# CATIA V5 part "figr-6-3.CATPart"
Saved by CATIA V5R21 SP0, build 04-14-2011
Part number: Part1
Bounding box of the stored display mesh (mm): x -62.5 to 62.5, y -75 to 75, z 0 to 10
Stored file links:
  D:\CATIA V5R21 E-RESOURCES\CATIA-V5R21\catia-v5r21-prt\c06-catia-v5r21-prt\c06-catia-v5r21-figr-6-3.CATPart
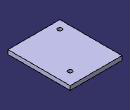
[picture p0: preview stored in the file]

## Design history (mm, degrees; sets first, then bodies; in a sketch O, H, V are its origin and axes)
Body1 (main body)
  Sketch1 on xy-plane, origin (0, 0, 0), H (1, 0, 0), V (0, 1, 0)
    line L1 (-62.5, 75) -> (62.5, 75)
    line L2 (62.5, 75) -> (62.5, -75)
    line L3 (62.5, -75) -> (-62.5, -75)
    line L4 (-62.5, -75) -> (-62.5, 75)
    axis line L5 (62.5, -75) -> (-62.5, 75)
    length L2 = 150
    length L3 = 125
    horizontal: L1 H, L3 H
    vertical: L2 V, L4 V
    midpoint: O L5
  Pad1: profile Sketch1, direction (0, 0, 1), length 10
  Sketch2 on face of Pad1, origin (-17.8347, -51.2044, 10), H (1, 0, 0), V (0, 1, 0)
    point P1 (-24.6653, -3.7956)
    reference projected line E1 (-44.6653, -23.7956) -> (80.3347, -23.7956) from edge [face of Pad1 | face of Pad1]
    reference projected line E2 (-44.6653, 126.2044) -> (-44.6653, -23.7956) from edge [face of Pad1 | face of Pad1]
    distance P1 E1 = 20
    distance P1 E2 = 20
  Hole1: placed by Sketch2, at (-42.5, -55, 10) direction (0, 0, -1), diameter 10, through (limit type 3)
  Sketch3 on face of Pad1, origin (35.5503, 42.9865, 10), H (1, 0, 0), V (0, 1, 0)
    point P1 (-3.0503, 2.0135)
    reference projected line E1 (26.9497, -117.9865) -> (26.9497, 32.0135) from edge [face of Pad1 | face of Pad1]
    reference projected line E2 (26.9497, 32.0135) -> (-98.0503, 32.0135) from edge [face of Pad1 | face of Pad1]
    distance P1 E1 = 30
    distance P1 E2 = 30
  Hole2: placed by Sketch3, at (32.5, 45, 10) direction (0, 0, -1), diameter 10, through (limit type 3)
